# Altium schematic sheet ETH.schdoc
size 297 x 209 mm; Symbol: Drawing-Symbol_A4; Company: 嘉立创EDA; Version: V1.0; Page Size: A4; @Project Name: New Project_2025-01-23_00-40-50; @Page Count: 4; @Update Date: 2025-08-03; @Create Date: 2025-07-30; @Schematic Name: Schematic3_7; @Page No: 3; @Page Name: IO; @Create Time: 15:34:36; @Update Time: 01:53:56; Border: 1; Width: 1170; Height: 825; Region Start: 1; X Region Count: 6; Y Region Count: 4; Blade Width: 10; Title Block Position: 3; @Board Name: cm4; Device: Drawing-Symbol_A4
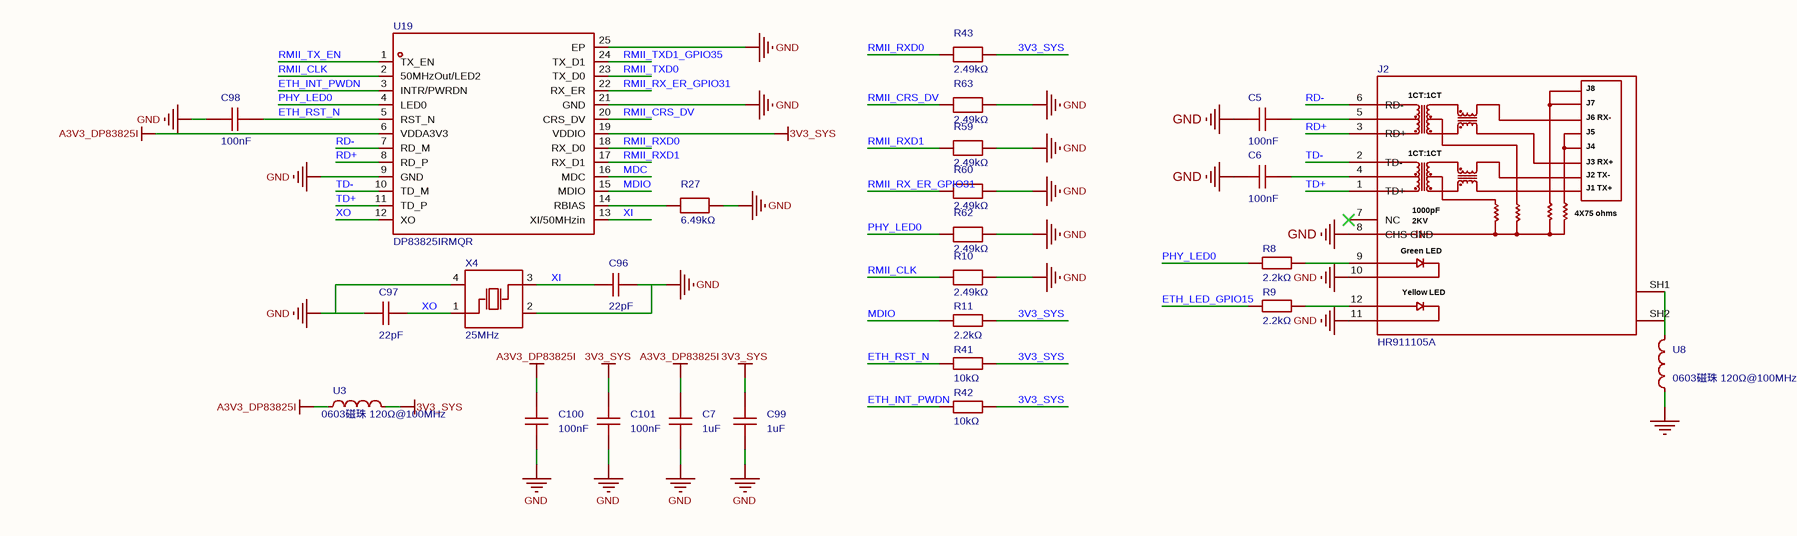
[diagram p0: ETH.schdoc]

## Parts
C5  100nF  [C0402 去耦电容]
C6  100nF  [C0402 去耦电容]
C7  1uF  [C0603]
C96  22pF  [C0402]
C97  22pF  [C0402]
C98  100nF  [C0402 去耦电容]
C99  1uF  [C0603]
C100  100nF  [C0402 去耦电容]
C101  100nF  [C0402 去耦电容]
J2  HR911105A  [RJ45-TH_HR911105A]
R8  2.2kΩ  [R0402]
R9  2.2kΩ  [R0402]
R10  2.49kΩ  [R0402]
R11  2.2kΩ  [R0402]
R27  6.49kΩ  [R0402]
R41  10kΩ  [R0402]
R42  10kΩ  [R0402]
R43  2.49kΩ  [R0402]
R59  2.49kΩ  [R0402]
R60  2.49kΩ  [R0402]
R62  2.49kΩ  [R0402]
R63  2.49kΩ  [R0402]
U3  LCSC Part Name: 0603磁珠 120Ω@100MHz  [L0603]  (hidden comment: BLM18PG121SN1D)
U8  LCSC Part Name: 0603磁珠 120Ω@100MHz  [L0603]  (hidden comment: BLM18PG121SN1D)
U19  DP83825IRMQR  [HVQFN-24_L3.0-W3.0-P0.40-TL-EP1.9]
X4  25MHz  [CRYSTAL-SMD_4P-L3.2-W2.5-BL]

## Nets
3V3_SYS: C99.2 C101.2 R11.2 R41.2 R42.2 R43.2 U3.2 U19.19(VDDIO)
A3V3_DP83825I: C7.2 C100.2 U3.1 U19.6(VDDA3V3)
GND: C5.1 C6.1 C7.1 C96.2 C97.1 C98.1 C99.1 C100.1 C101.1 J2.8(CHS_GND) J2.10 J2.11 R10.2 R27.2 R59.2 R60.2 R62.2 R63.2 U8.1 U19.9(GND) U19.21(GND) U19.25(EP) X4.2(GND) X4.4(GND)
ETH_INT_PWDN: R42.1 U19.3(INTR/PWRDN)
ETH_LED_GPIO15: R9.1
ETH_RST_N: C98.2 R41.1 U19.5(RST_N)
MDC: U19.16(MDC)
MDIO: R11.1 U19.15(MDIO)
PHY_LED0: R8.1 R62.1 U19.4(LED0)
RD+: J2.3(RD+) U19.8(RD_P)
RD-: J2.6(RD-) U19.7(RD_M)
RMII_CLK: R10.1 U19.2(50MHzOut/LED2)
RMII_CRS_DV: R63.1 U19.20(CRS_DV)
RMII_RX_ER_GPIO31: R60.1 U19.22(RX_ER)
RMII_RXD0: R43.1 U19.18(RX_D0)
RMII_RXD1: R59.1 U19.17(RX_D1)
RMII_TX_EN: U19.1(TX_EN)
RMII_TXD0: U19.23(TX_D0)
RMII_TXD1_GPIO35: U19.24(TX_D1)
TD+: J2.1(TD+) U19.11(TD_P)
TD-: J2.2(TD-) U19.10(TD_M)
XI: C96.1 U19.13(XI/50MHzin) X4.3(OSC2)
XO: C97.2 U19.12(XO) X4.1(OSC1)
NetC5_2: C5.2 J2.5
NetC6_2: C6.2 J2.4
NetJ2_9: J2.9 R8.2
NetJ2_12: J2.12 R9.2
NetJ2_SH1: J2.SH1 J2.SH2 U8.2
NetR27_1: R27.1 U19.14(RBIAS)

Not connected (* = marked no-connect by the designer): J2 7(NC)*

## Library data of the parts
C5 C6 = CL05B104KO5NNNC: 容值:100nF;精度:±10%;额定电压:16V;温度系数:X7R;; Manufacturer: SAMSUNG(三星); Check: false; Add into BOM: yes; 3D Model: ac125912035d415993ca9572d50418b1; 3D Model Transform: 39.37,19.685,0,0,0,0,0,0,0; Tolerance: ±10%; Temperature Coefficient: X7R; Voltage Rating: 16V; ModelName: C0402_L1.0-W0.5-H0.5
C7 C99 = CGA0603X5R105K500JT: 容值:1uF;精度:±10%;额定电压:50V;温度系数:X5R;; Manufacturer: HRE(芯声); Add into BOM: yes; 3D Model: ac125912035d415993ca9572d50418b1; 3D Model Transform: 62.992,31.496,0,0,0,0,0,0,0; Tolerance: ±10%; Voltage Rating: 50V; Temperature Coefficient: X5R; ModelName: C0603_L1.6-W0.8-H0.8
C96 C97 = 0402CG220J500NT: 容值:22pF;精度:±5%;额定电压:50V;温度系数:C0G;; Manufacturer: FH(风华); Add into BOM: yes; 3D Model: 36a51122f27c49738f86b3bfa98863e0; 3D Model Transform: 39.37,19.685,0,0,0,0,0,0,0; Tolerance: ±5%; Voltage Rating: 50V; Temperature Coefficient: C0G; ModelName: C0402_L1.0-W0.5-H0.5
C98 C100 = CL05B104KO5NNNC: 容值:100nF;精度:±10%;额定电压:16V;温度系数:X7R;; Manufacturer: SAMSUNG(三星); Check: false; Add into BOM: yes; 3D Model: ac125912035d415993ca9572d50418b1; 3D Model Transform: 39.37,19.685,0,0,0,0,0,0,0; Tolerance: ±10%; Voltage Rating: 16V; Temperature Coefficient: X7R; ModelName: C0402_L1.0-W0.5-H0.5
C101 = CL05B104KO5NNNC: 容值:100nF;精度:±10%;额定电压:16V;温度系数:X7R;; Manufacturer: SAMSUNG(三星); Add into BOM: yes; 3D Model: ac125912035d415993ca9572d50418b1; 3D Model Transform: 39.37,19.685,0,0,0,0,0,0,0; Tolerance: ±10%; Voltage Rating: 16V; Check: false; Temperature Coefficient: X7R; ModelName: C0402_L1.0-W0.5-H0.5
J2 = HR911105A_C12074: 连接器类型:RJ45插座;安装方式:弯插;端口数量:1;LED:带LED;屏蔽:有屏蔽;等级:-;触头材质:磷青铜;触头镀层:金;工作温度:0℃~+70℃;; Manufacturer: HANRUN(汉仁); 3D Model: 269ece015cf14129b359f9a66aa2dc0d0819f05c4eef4c71ace90d822a990e87; 3D Model Transform: 624.711,850.392,0,0,0,0,0,-89.567,-129.921; Connector Type: RJ45插座; Number of Ports: 1; LED: 带LED; Shielding: 有屏蔽; PoE: 不带PoE; Supplementary Features: 带滤波; AddInBom: yes
R8 R9 R11 = 0402WGF2201TCE: 电阻类型:厚膜电阻;阻值:2.2kΩ;精度:±1%;功率:62.5mW;工作电压:50V;温度系数:±100ppm/℃;; Manufacturer: UNI-ROYAL(厚声); Add into BOM: yes; 3D Model: 98c88bc2b9094f218f3a3e30a7012738; 3D Model Transform: 39.37,19.685,0,0,0,0,0,0,0; Tolerance: ±1%; Power(Watts): 62.5mW; Voltage-Supply(Max): 50V; ModelName: R0402_L1.0-W0.5-H0.4
R10 R43 R59 R60 R62 R63 = FRC0402F2491TS: 电阻类型:厚膜电阻;阻值:2.49kΩ;精度:±1%;功率:62.5mW;工作电压:50V;温度系数:±100ppm/℃;; Manufacturer: FOJAN(富捷); Add into BOM: yes; 3D Model: 98c88bc2b9094f218f3a3e30a7012738; 3D Model Transform: 39.37,19.685,0,0,0,0,0,0,0; Tolerance: ±1%; Power(Watts): 62.5mW; Voltage-Supply(Max): 50V; ModelName: R0402_L1.0-W0.5-H0.4
R27 = FRC0402F6491TS: 电阻类型:厚膜电阻;阻值:6.49kΩ;精度:±1%;功率:62.5mW;工作电压:50V;温度系数:±100ppm/℃;; Manufacturer: FOJAN(富捷); Add into BOM: yes; 3D Model: 98c88bc2b9094f218f3a3e30a7012738; 3D Model Transform: 39.37,19.685,0,0,0,0,0,0,0; Tolerance: ±1%; Power(Watts): 62.5mW; Voltage-Supply(Max): 50V; ModelName: R0402_L1.0-W0.5-H0.4
R41 R42 = 0402WGF1002TCE: 电阻类型:厚膜电阻;阻值:10kΩ;精度:±1%;功率:62.5mW;工作电压:50V;温度系数:±100ppm/℃;; Manufacturer: UNI-ROYAL(厚声); Add into BOM: yes; 3D Model: 98c88bc2b9094f218f3a3e30a7012738; 3D Model Transform: 39.37,19.685,0,0,0,0,0,0,0; Tolerance: ±1%; Power(Watts): 62.5mW; Voltage-Supply(Max): 50V; ModelName: R0402_L1.0-W0.5-H0.4
U3 U8 = BLM18PG121SN1D: 标称阻抗@测试频率:120Ω@100MHz;误差:±25%;直流电阻(RDC):50mΩ;; Manufacturer: muRata(村田); Symbol: BLM18PG121SN1D_C14709; 3D Model: 2bc5ec593d464d6ba9807aec0b5673c2; 3D Model Transform: 62.992,31.496,0,180,0,0,0.094,0.629,0; Tolerance: ±25%; DC Resistance: 50mΩ; Current Rating: 2A; Circuits: 1; AddInBom: yes; ModelName: L0603_L1.6-W0.8-H0.5_BEAD
U19 = DP83825IRMQR: 应用功能:-;通道数:-;MAC接口:RMII;; Manufacturer: TI(德州仪器); 3D Model: 80b71bc00fd84f0b98c58542b88e20c70819f05c4eef4c71ace90d822a990e87; 3D Model Transform: 118.8974,118.8974,0,0,0,0,0,0,0; MAC Interface: RMII; Voltage - Supply: 1.8V；3.3V; AddInBom: yes
X4 = X322525MOB4SI: 晶振类型:贴片晶振;频率:25MHz;常温频差:±10ppm;负载电容:12pF;频率稳定度:±20ppm;; Manufacturer: YXC(扬兴晶振); 3D Model: ff2dfd5650294453a14147960efe18380819f05c4eef4c71ace90d822a990e87; 3D Model Transform: 125.984,98.425,0,0,0,0,0,0,0; Normal temperature Frequency Tolerance: ±10ppm; Load Capacitance: 12pF; Frequency Stability: ±20ppm; AddInBom: yes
